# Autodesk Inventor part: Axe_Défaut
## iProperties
Shininess: 64.0
Length Units: 11269
Angle Units: 11279
Time Units: 11290
Mass Units: 11283
Length Display Precision: 3
Angle Display Precision: 2
Compacted: True
Part Number: Axe_Défaut
Document SubType Name: Modeling
Created: 2006-01
Material: Par défaut
Designer: Fricot
Density: 0.0
Volumn: 0.0
Area: 0.0
PropertySet Name: Model Information
Control State: 0
Master: False
Checked Out: False
Author: Fricot
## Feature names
1. Base1
